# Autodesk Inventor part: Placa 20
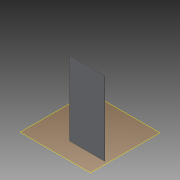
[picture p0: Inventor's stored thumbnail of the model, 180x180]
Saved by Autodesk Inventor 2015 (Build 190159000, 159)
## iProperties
Created: 2015-04
Part Number: Placa 20
Material: Generic
Document SubType Name: Modeling
Designer: suporte
Density: 1 g/cm^3
Appearance: Default
Author: suporte
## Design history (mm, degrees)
workplane "Work Plane1"
sketch "Sketch1"
  geometry: L1 (912.5, -500)-(-87.5, -500) reference; L2 (912.5, -487.5)-(-87.5, -487.5); L3 (-87.5, -487.5)-(-87.5, -500); L4 (-87.5, -500)-(912.5, -500); L5 (912.5, -500)-(912.5, -487.5); 1 further point
  constraints: 8 end point, 2 parallel, 1 horizontal, 1 perpendicular, 1 other
extrude "Extrusion1" new body sketch "Sketch1" distance "d0" = 2100; taper "d1" = 0 deg
body "Solid1"
node "Reference1"
